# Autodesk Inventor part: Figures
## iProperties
Shininess: 65.0
Angle Display Precision: 2
Document Length Units: 11269
Document Angle Units: 11279
Document Time Units: 11290
Document Mass Units: 11283
Document Length Units Precision: 3
Document Angle Units Precision: 2
Created: 2001-11
Part Number: Figures
Document SubType Name: Modeling
Designer: Renu Muthoo
Density: 1 g/cm^3
Density: 0.0
Volumn: 0.0
Area: 0.0
PropertySet Name: Model Information
Control State: 0
Master: False
Checked Out: False
Author: Renu Muthoo
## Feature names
1. Extrusion1
2. Extrusion2
3. Extrusion3
4. Hole1
